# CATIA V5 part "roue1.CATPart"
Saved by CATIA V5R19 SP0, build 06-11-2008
Part number: roue1
Bounding box of the stored display mesh (mm): x 220 to 780, y -10 to 550, z -45 to 30
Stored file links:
  C:\Users\Thibaud\Desktop\IFMA\thinkmotion\IAO\modele_catia\roue1.CATPart
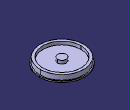
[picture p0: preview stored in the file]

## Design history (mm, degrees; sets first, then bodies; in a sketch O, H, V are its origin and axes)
Body1 (main body)
  Plane1: stored without definition
  Circle1 "contour_roue1": stored without definition
  Sketch1 on Plane1, origin (0, 0, 0), H (1, 0, 0), V (0, 1, 0)
    circle A1 centre (500, 270) radius 266.8333
    reference projected circle E1 centre (500, 270) radius 266.8333 from Circle1
    coincidence: A1 E1
  Pad1: profile Sketch1, direction (0, 0, 1), length 30, mirrored extent
  Line1 "axe_pivot_roue1_batit": stored without definition
  Sketch2 on start face of Pad1, origin (0, 0, -30), H (1, 0, 0), V (0, -1, 0)
    circle A1 centre (500, -270) radius 280
    point P1 (500, -270)
    reference projected point E1 (500, -270) from Line1
    radius A1 = 280
    coincidence: E1 P1
  Pad2: profile Sketch2, direction (0, 0, -1), length 15
  Line2 "axe_pivot_roue1_batit": stored without definition
  Sketch3 on end face of Pad1, origin (0, 0, 30), H (1, 0, 0), V (0, 1, 0)
    circle A1 centre (500, 270) radius 235
    point P1 (500, 270)
    reference projected point E1 (500, 270) from Line2
    circle A2 centre (500, 270) radius 52.5
    radius A1 = 235
    radius A2 = 52.5
    coincidence: P1 E1
    concentricity: A2 A1
  Pocket1: profile Sketch3, direction (0, 0, -1), length 40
